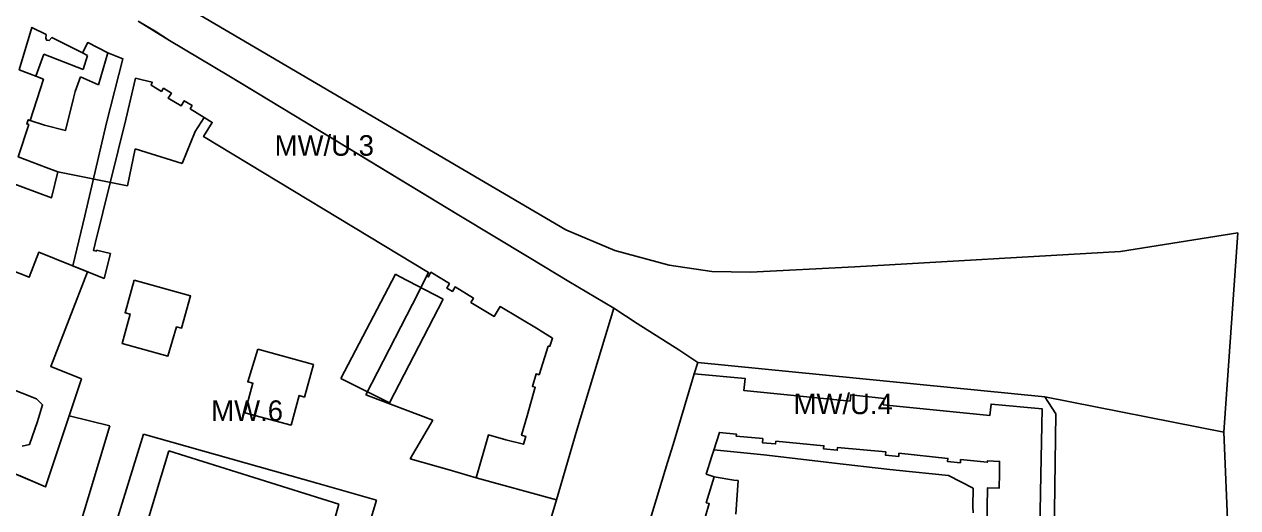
# Model space of a CAD drawing. Extents: x 7424052 to 7425705, y 5546602 to 5547569.
# Drawn here: x 7425164.6 to 7425459.5, y 5547281.2 to 5547398.7 of the extents above; entities that cross this region are included whole.
import ezdxf

# ---------------------------------------------------------------- set-up
doc = ezdxf.new("R2010")
doc.units = 0
for name, color, linetype in [('linie rozgraniczające', 7, 'Continuous'), ('nieprzekraczalne linie zabudowy', 7, 'Continuous'), ('obowiazujace linie zabudowy', 7, 'Continuous'), ('przeznaczenia terenów', 7, 'Continuous')]:
    doc.layers.add(name, color=color, linetype=linetype)

msp = doc.modelspace()

# ---------------------------------------------------------------- linework, layer by layer
at = {"layer": 'linie rozgraniczające'}
for p, q in [((7425181.98, 5547415.77), (7425296.22, 5547348.71)), ((7425199.86, 5547394.71), (7425192.26, 5547399.44)), ((7425214.28, 5547386.14), (7425199.86, 5547394.71)), ((7425216.31, 5547384.91), (7425214.28, 5547386.14)), ((7425270.19, 5547352.29), (7425216.31, 5547384.91)), ((7425206.12, 5547372.58), (7425208.3, 5547376.02)), ((7425210.24, 5547374.83), (7425208.14, 5547371.36)), ((7425208.3, 5547376.02), (7425210.24, 5547374.83)), ((7425202.97, 5547364.82), (7425206.12, 5547372.58)), ((7425208.14, 5547371.36), (7425262.84, 5547338.38)), ((7425189.66, 5547359.39), (7425191.49, 5547368.36)), ((7425191.49, 5547368.36), (7425202.97, 5547364.82)), ((7425163.09, 5547366.42), (7425169.9, 5547363.89)), ((7425169.9, 5547363.89), (7425172.71, 5547362.84)), ((7425172.71, 5547362.84), (7425189.66, 5547359.39)), ((7425287.24, 5547341.98), (7425270.19, 5547352.29)), ((7425296.22, 5547348.71), (7425308.13, 5547343.73)), ((7425430.95, 5547343.41), (7425459.48, 5547347.99)), ((7425459.48, 5547347.99), (7425456.07, 5547299.57)), ((7425296.95, 5547336.19), (7425287.24, 5547341.98)), ((7425308.13, 5547343.73), (7425321.3, 5547340.09)), ((7425366.43, 5547339.69), (7425430.95, 5547343.41)), ((7425262.84, 5547338.38), (7425258.9, 5547330.62)), ((7425321.3, 5547340.09), (7425331.69, 5547338.57)), ((7425331.69, 5547338.57), (7425341.06, 5547338.4)), ((7425341.06, 5547338.4), (7425366.43, 5547339.69)), ((7425307.85, 5547329.66), (7425296.95, 5547336.19)), ((7425258.9, 5547330.62), (7425247.55, 5547308.64)), ((7425298.89, 5547299.99), (7425307.85, 5547329.66)), ((7425307.85, 5547329.66), (7425313.53, 5547325.95)), ((7425313.53, 5547325.95), (7425323.66, 5547319.59)), ((7425323.66, 5547319.59), (7425328.29, 5547316.5)), ((7425327.37, 5547313.74), (7425328.29, 5547316.5)), ((7425328.29, 5547316.5), (7425412.57, 5547308.16)), ((7425322.29, 5547296.54), (7425326.95, 5547312.31)), ((7425326.95, 5547312.31), (7425327.37, 5547313.74)), ((7425247.55, 5547308.64), (7425263.86, 5547302.47)), ((7425456.07, 5547299.57), (7425412.57, 5547308.16)), ((7425412.57, 5547308.16), (7425415.3, 5547303.98)), ((7425263.86, 5547302.47), (7425258.37, 5547293.06)), ((7425415.3, 5547303.98), (7425414.81, 5547272.98)), ((7425293.89, 5547283.1), (7425298.89, 5547299.99)), ((7425458.68, 5547239.81), (7425456.07, 5547299.57)), ((7425193.55, 5547299.05), (7425181.63, 5547260.6)), ((7425235.98, 5547287.06), (7425193.55, 5547299.05)), ((7425320.91, 5547292.15), (7425322.29, 5547296.54)), ((7425331.69, 5547293.68), (7425330.29, 5547289.3)), ((7425332.17, 5547295.15), (7425331.69, 5547293.68)), ((7425332.19, 5547295.21), (7425332.17, 5547295.15)), ((7425344.31, 5547294.07), (7425332.19, 5547295.21)), ((7425346.44, 5547293.77), (7425344.31, 5547294.07)), ((7425359.43, 5547292.28), (7425346.44, 5547293.77)), ((7425258.37, 5547293.06), (7425265.23, 5547291.13)), ((7425265.23, 5547291.13), (7425267.81, 5547290.4)), ((7425316.21, 5547276.67), (7425320.91, 5547292.15)), ((7425361.49, 5547292), (7425359.43, 5547292.28)), ((7425374.22, 5547290.53), (7425361.49, 5547292)), ((7425267.81, 5547290.4), (7425274.37, 5547288.42)), ((7425274.37, 5547288.42), (7425293.89, 5547283.1)), ((7425330.29, 5547289.3), (7425332.21, 5547288.72)), ((7425332.21, 5547288.72), (7425336.99, 5547287.9)), ((7425336.99, 5547287.9), (7425338.05, 5547287.8)), ((7425338.05, 5547287.8), (7425337.46, 5547279.59)), ((7425376.5, 5547290.32), (7425374.22, 5547290.53)), ((7425389.16, 5547289.03), (7425376.5, 5547290.32)), ((7425395.2, 5547285.96), (7425389.16, 5547289.03)), ((7425250.17, 5547283.05), (7425235.98, 5547287.06)), ((7425395.12, 5547281.49), (7425395.2, 5547285.96)), ((7425244.57, 5547264.62), (7425250.17, 5547283.05)), ((7425293.89, 5547283.1), (7425290.81, 5547272.76)), ((7425395.16, 5547279.91), (7425395.12, 5547281.49))]:
    msp.add_line(p, q, dxfattribs=at)
at = {"layer": 'nieprzekraczalne linie zabudowy'}
for p, q in [((7425179.99, 5547394.2), (7425178.72, 5547391.69)), ((7425184.84, 5547391.75), (7425179.99, 5547394.2)), ((7425169.34, 5547391.42), (7425167.38, 5547386.04)), ((7425178.91, 5547387.66), (7425169.34, 5547391.42)), ((7425178.72, 5547391.69), (7425179.92, 5547391.12)), ((7425179.92, 5547391.12), (7425178.91, 5547387.66)), ((7425182.58, 5547383.97), (7425184.84, 5547391.75)), ((7425169.24, 5547385.31), (7425165.98, 5547375.31)), ((7425167.38, 5547386.04), (7425169.24, 5547385.31)), ((7425176.91, 5547382.31), (7425178.24, 5547385.87)), ((7425178.24, 5547385.87), (7425182.58, 5547383.97)), ((7425176.52, 5547380.7), (7425176.91, 5547382.31)), ((7425174.6, 5547372.88), (7425176.52, 5547380.7)), ((7425165.98, 5547375.31), (7425169.46, 5547374.14)), ((7425169.46, 5547374.14), (7425174.6, 5547372.88)), ((7425254.77, 5547337.95), (7425241.53, 5547312.62)), ((7425255.78, 5547337.41), (7425254.77, 5547337.95)), ((7425266.37, 5547331.87), (7425255.78, 5547337.41)), ((7425253.34, 5547306.71), (7425266.37, 5547331.87)), ((7425241.53, 5547312.62), (7425253.34, 5547306.71)), ((7425175.48, 5547303.54), (7425169.76, 5547286.23)), ((7425185.39, 5547301.08), (7425175.48, 5547303.54)), ((7425176.58, 5547272.07), (7425185.39, 5547301.08)), ((7425199.7, 5547294.97), (7425196.81, 5547285.4)), ((7425241.02, 5547282.04), (7425199.7, 5547294.97)), ((7425169.76, 5547286.23), (7425161.98, 5547289.55)), ((7425238.32, 5547272.41), (7425241.02, 5547282.04))]:
    msp.add_line(p, q, dxfattribs=at)
at = {"layer": 'obowiazujace linie zabudowy'}
for points in [[(7425160.76, 5547360.35), (7425171.22, 5547356.51), (7425172.71, 5547362.84), (7425169.9, 5547363.89), (7425163.09, 5547366.42), (7425165.65, 5547374.29), (7425165.19, 5547374.45), (7425165.52, 5547375.46), (7425165.98, 5547375.31), (7425169.24, 5547385.31), (7425167.38, 5547386.04), (7425163.36, 5547387.61), (7425166.42, 5547397.9), (7425169.89, 5547396.16), (7425169.78, 5547395.19), (7425170.02, 5547394.78), (7425170.64, 5547394.74), (7425171.23, 5547395.42), (7425178.72, 5547391.69), (7425179.99, 5547394.2), (7425184.84, 5547391.75), (7425188.55, 5547390.31), (7425184.55, 5547374.7), (7425179.25, 5547352.12), (7425176.36, 5547339.98), (7425184, 5547336.92), (7425185.49, 5547342.94), (7425182.14, 5547343.77), (7425182.08, 5547343.53), (7425181.37, 5547343.71), (7425181.77, 5547345.4), (7425189.28, 5547375.49), (7425191.6, 5547385.59)], [(7425191.6, 5547385.59), (7425193.24, 5547385.16), (7425195.66, 5547384.57), (7425195.38, 5547383.89), (7425197.91, 5547382.37), (7425198.42, 5547383.13), (7425200.33, 5547381.96), (7425199.56, 5547380.69), (7425202.66, 5547378.83), (7425203.45, 5547380.1), (7425205.35, 5547378.91), (7425204.89, 5547378.16), (7425208.3, 5547376.02), (7425210.24, 5547374.83), (7425208.14, 5547371.36), (7425262.84, 5547338.38), (7425262.39, 5547337.43), (7425262.82, 5547337.28), (7425263.41, 5547338.39), (7425267.9, 5547335.64), (7425267.25, 5547334.56), (7425268.61, 5547333.73), (7425269.27, 5547334.84), (7425273.74, 5547332.12), (7425273.13, 5547331.09), (7425278.78, 5547327.66), (7425280.2, 5547330.06), (7425289.49, 5547324.57), (7425289.95, 5547324.28), (7425292.96, 5547322.37), (7425292.31, 5547320.41), (7425291.9, 5547320.42), (7425289.7, 5547313.5), (7425288.97, 5547313.71), (7425288.05, 5547310.68), (7425288.75, 5547310.47), (7425286.81, 5547303.5), (7425285.42, 5547298.83), (7425286.47, 5547298.52), (7425285.93, 5547296.59), (7425281.64, 5547297.72), (7425277.35, 5547298.86), (7425274.37, 5547288.42), (7425293.89, 5547283.1), (7425298.89, 5547299.99), (7425307.85, 5547329.66), (7425296.95, 5547336.19), (7425287.24, 5547341.98), (7425270.19, 5547352.29), (7425245.85, 5547367.03), (7425214.28, 5547386.14), (7425199.86, 5547394.71), (7425199.86, 5547394.71), (7425196.37, 5547397.03), (7425192.26, 5547399.44)], [(7425163.14, 5547289.06), (7425165.41, 5547288.09), (7425169.76, 5547286.23), (7425178.44, 5547312.5), (7425171.01, 5547315.54), (7425179.93, 5547338.5), (7425168.1, 5547343.28), (7425165.76, 5547337.2), (7425156.6, 5547340.77)], [(7425191.29, 5547336.52), (7425189.06, 5547328.57), (7425190.33, 5547328.22), (7425188.35, 5547321.09), (7425199.48, 5547318.02), (7425201.57, 5547325.12), (7425202.81, 5547324.82), (7425205, 5547332.67), (7425191.29, 5547336.52)], [(7425221.35, 5547319.71), (7425218.88, 5547311.81), (7425220.15, 5547311.45), (7425218.2, 5547304.27), (7425229.4, 5547301.25), (7425231.36, 5547308.43), (7425232.64, 5547308.08), (7425234.82, 5547315.99), (7425221.35, 5547319.71)], [(7425150.83, 5547314.18), (7425167.56, 5547307.61), (7425169.03, 5547306.17), (7425167.76, 5547302.1), (7425165.81, 5547296.53), (7425164.05, 5547296.15)], [(7425411.28, 5547271.31), (7425411.64, 5547289.21), (7425411.95, 5547305.21), (7425399.53, 5547306.35), (7425399.27, 5547303.61), (7425373.32, 5547306.2), (7425373.52, 5547307.75), (7425365.43, 5547308.59), (7425365.26, 5547307.11), (7425339.43, 5547309.69), (7425339.79, 5547312.57), (7425327.37, 5547313.74), (7425326.95, 5547312.31), (7425322.29, 5547296.54), (7425320.91, 5547292.15), (7425316.21, 5547276.67)], [(7425330.29, 5547289.3), (7425330.29, 5547289.3), (7425331.69, 5547293.68), (7425332.17, 5547295.15), (7425333.5, 5547299.48), (7425337.64, 5547299.09), (7425337.59, 5547298.57), (7425344.06, 5547297.97), (7425343.97, 5547296.99), (7425347.17, 5547296.7), (7425347.23, 5547297.34), (7425358.91, 5547296.26), (7425358.83, 5547295.46), (7425362.16, 5547295.16), (7425362.22, 5547295.84), (7425373.95, 5547294.75), (7425373.88, 5547293.93), (7425377.11, 5547293.63), (7425377.15, 5547294.43), (7425389.03, 5547293.18), (7425388.98, 5547292.41), (7425392.08, 5547292.13), (7425392.12, 5547292.89), (7425398.61, 5547292.24), (7425398.63, 5547292.56), (7425401.58, 5547292.42), (7425401.54, 5547289.47), (7425401.5, 5547285.95), (7425398.65, 5547285.99), (7425398.46, 5547271.56)], [(7425330.15, 5547279.17), (7425331.04, 5547282.19), (7425330.31, 5547282.38), (7425332.21, 5547288.72), (7425330.29, 5547289.3)], [(7425196.81, 5547285.4), (7425192.23, 5547270.21), (7425200.55, 5547267.75), (7425201.69, 5547271.37), (7425235.23, 5547261.37), (7425238.32, 5547272.41)]]:
    msp.add_lwpolyline(points, dxfattribs=at)

# ---------------------------------------------------------------- texts
at = {"layer": 'przeznaczenia terenów'}
for s, p in [('MW/U.3', (7425225.41, 5547366.72)), ('MW/U.4', (7425351.52, 5547303.92)), ('MW.6', (7425210, 5547302.27))]:
    msp.add_text(s, height=5, dxfattribs=at).set_placement(p)

doc.saveas('drawing.dxf')
